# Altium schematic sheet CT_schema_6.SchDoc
size 278 x 170 mm
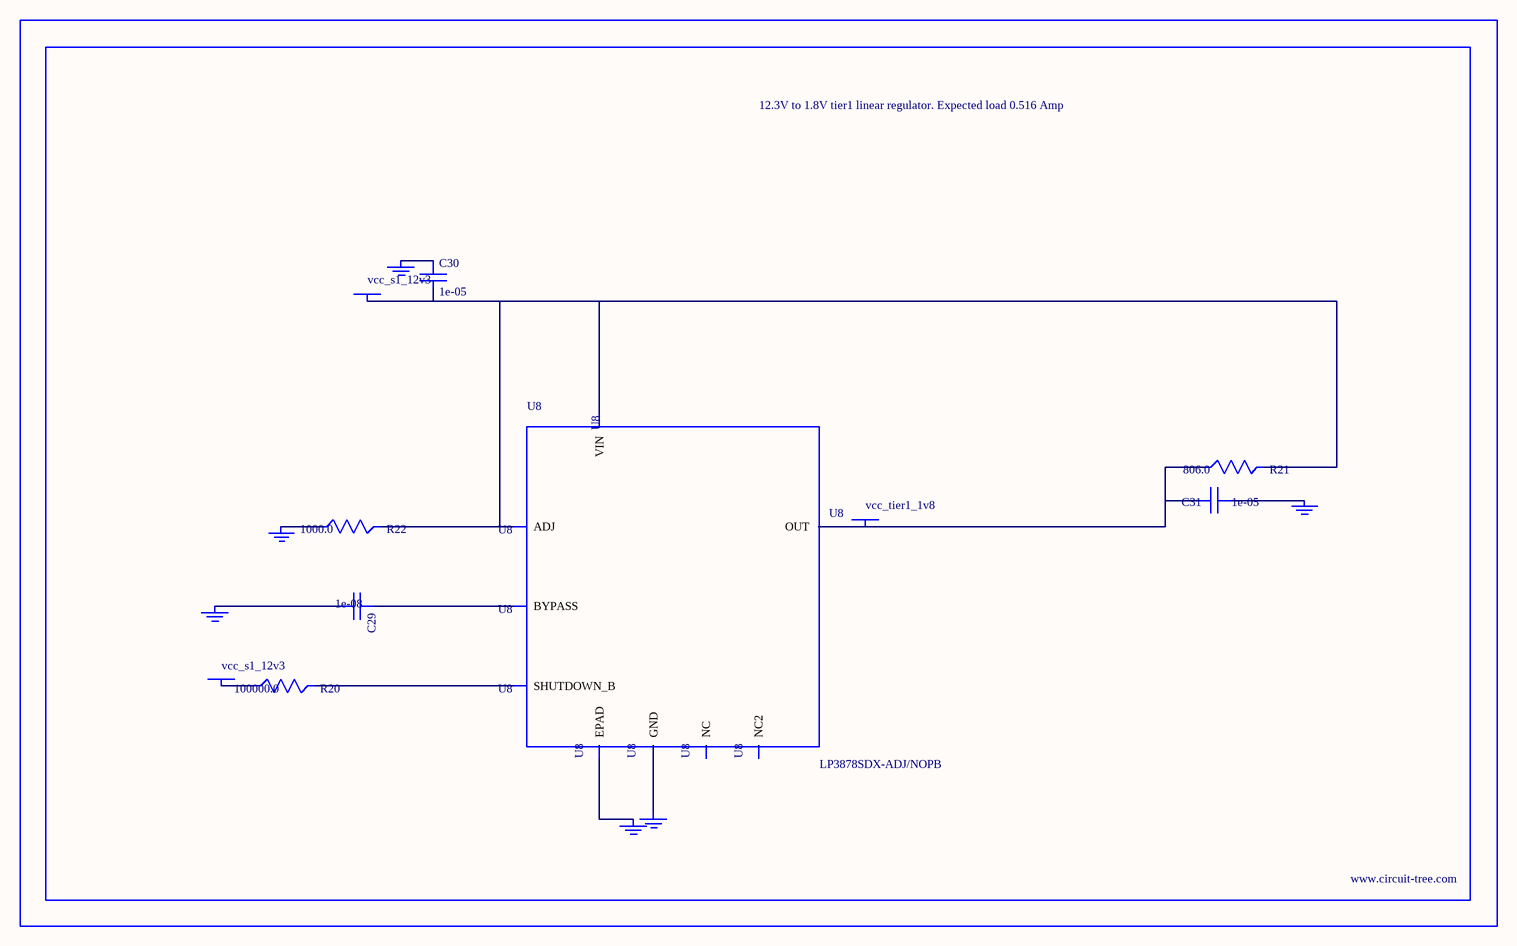
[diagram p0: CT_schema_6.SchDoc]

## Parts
BORDER5  (no value)
C29  1e-08  [C0402]
C30  1e-05  [C1210]
C31  1e-05  [C0805]
GND_INSTANCE_5_0  (no value)
GND_INSTANCE_5_1  (no value)
GND_INSTANCE_5_2  (no value)
GND_INSTANCE_5_3  (no value)
GND_INSTANCE_5_4  (no value)
GND_INSTANCE_5_5  (no value)
POWER_INSTANCE_5_0  vcc_s1_12v3
POWER_INSTANCE_5_1  vcc_s1_12v3
POWER_INSTANCE_5_2  vcc_tier1_1v8
R20  100000.0  [R0603]
R21  806.0  [R0603]
R22  1000.0  [R0603]
U8  LP3878SDX-ADJ/NOPB  [WSON-8]

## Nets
NetC29_1: C29.1 U8.1(BYPASS)
NetC29_2: C29.2 GND_INSTANCE_5_0.0(GND)
NetC30_1: C30.1 GND_INSTANCE_5_1.0(GND)
NetC30_2: C30.2 POWER_INSTANCE_5_0.0(PWR) R21.2 R22.2 U8.4(VIN) U8.6(ADJ)
NetC31_1: C31.1 GND_INSTANCE_5_2.0(GND)
NetC31_2: C31.2 POWER_INSTANCE_5_2.0(PWR) R21.1 U8.5(OUT)
NetGND_INSTANCE_5_3_0: GND_INSTANCE_5_3.0(GND) R22.1
NetGND_INSTANCE_5_4_0: GND_INSTANCE_5_4.0(GND) U8.PAD(EPAD)
NetGND_INSTANCE_5_5_0: GND_INSTANCE_5_5.0(GND) U8.3(GND)
NetPOWER_INSTANCE_5_1_0: POWER_INSTANCE_5_1.0(PWR) R20.1
NetR20_2: R20.2 U8.8(SHUTDOWN_B)

Not connected (* = marked no-connect by the designer): U8 2(NC) 7(NC2)

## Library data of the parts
BORDER5 = BORDER_PAGE5
C29 = C0402C103K3RAC
C30 = C1210C106K5PACTU
C31 = GRM219R60J106ME19D
GND_INSTANCE_5_0-GND_INSTANCE_5_5 = GND
POWER_INSTANCE_5_0-POWER_INSTANCE_5_2 = PWR
R20 = RC0603JR-07100KL
R21 = ERJ-3EKF8060V
R22 = RC0603JR-071KL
